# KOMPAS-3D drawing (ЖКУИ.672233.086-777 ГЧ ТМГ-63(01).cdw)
File: created 02.07.2014 17:53:00, last saved 31.01.2023 17:05:09.
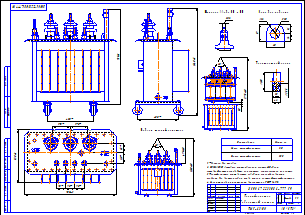
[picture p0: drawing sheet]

Sheet 1: A2, landscape

Title block, sheet 1: name: Трансформатор / Габаритный чертеж; designation: ЖКУИ.672233.086 - 777   ГЧ; material: ТМГ-63(01); mass: См.табл; scale: 1:1; sheets: 1; organisation: АО "КТЗ"; sheet format: A2; revision letter: А; stored path: D:\Documents\НОВЫЕ РАЗРАБОТКИ\ОВАЛЬНЫЕ\ТМГ-63 круглый\В цех до архива 09.06.14\Сборочный\ЖКУИ 672 233.086.cdw; drawn by: Куанышев

Views: Вид 3
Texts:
  1. *Размеры для справок
  2. ВНИМАНИЕ! Активная часть связана с крышкой. Подъем
  активной части производить за пластины, расположенные на крышке.
  3. Трансформатор поставляется заводом с запломбированными
  пробками для взятия пробы и слива масла и крышкой трансформатора
  4. Знак строповки и центр масс выполнить по ГОСТ 14192
  Масса, кг
  Масло  трансформатора
  Полная трансформатора
  Подъем трансформатора
  Шпилька ввода ВН и НН
  Крюк для подъема
  Транспортный ролик
  Стандартные изделия
  Гайка М10-6H (S16) ГОСТ 5916-70
  Гайка
  ГОСТ 5916-70
Dimensions and other numbers on the sheet: 80; 355; 12; 25,5; 35; 42; 100; 31; 26; 60; 30; 32; 57; 1775±10; 50; 495±10; 1130±10; 935±3; 450*; 400*; 1040±5; 900±3; 90; 85; 110; 170*; 520±3; 1:1; 1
